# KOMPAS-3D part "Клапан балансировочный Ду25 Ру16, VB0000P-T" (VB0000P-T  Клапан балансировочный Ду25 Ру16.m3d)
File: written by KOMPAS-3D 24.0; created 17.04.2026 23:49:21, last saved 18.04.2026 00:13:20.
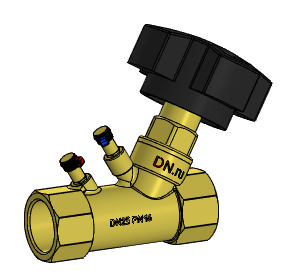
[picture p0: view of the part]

Document properties: Автор: tyuri; Полное имя файла: E:\Работа\Зайцев\АУТСОРС\Диман\Балансировка\VB0000P-T Клапан балансировочный DN.ru Ду15-50 Ру16\DN25\VB0000P-T  Клапан балансировочный Ду25 Ру16.m3d

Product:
- Body: Тело 2  | qty 1
    Масса: 1.063236
- Part/product: Клапан балансировочный Ду25 Ру16  | designation VB0000P-T
    Масса: 0.54
    Раздел спецификации: Прочие изделия
    Примечание: D080-01093

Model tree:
1. Операция без истории:1

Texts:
  VB0000P-T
